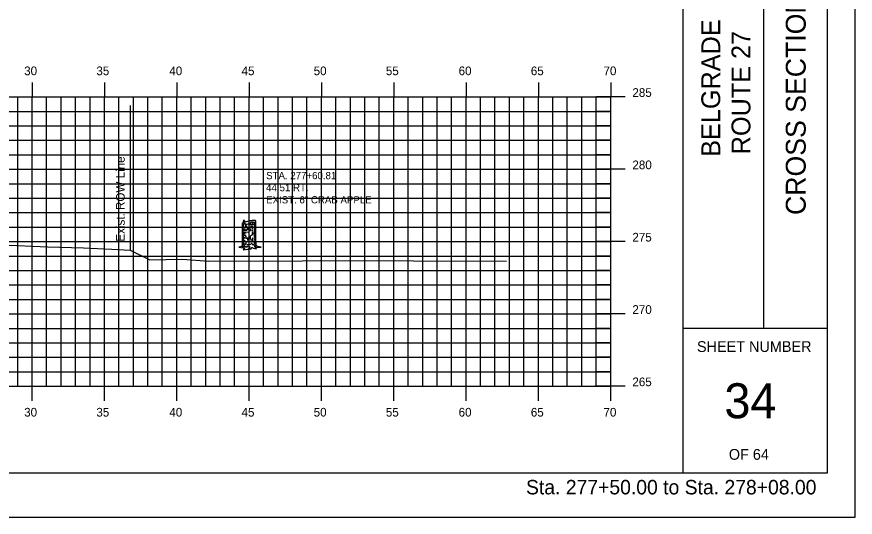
# Model space of a CAD drawing. Extents: x 854453 to 854623, y 366268 to 366378.
# Drawn here: x 854565.4 to 854623.3, y 366268.2 to 366302.8 of the extents above; entities that cross this region are included whole.
import ezdxf

# ---------------------------------------------------------------- set-up
doc = ezdxf.new("R2010")
doc.units = 0
for name, color, linetype in [('BORDER', 7, 'Continuous'), ('D_Text_Monospaced', 7, 'Continuous'), ('E_ROW_Line', 7, 'Continuous'), ('H_V ANNOTATION', 7, 'Continuous'), ('HIGHWAY_TITLE', 7, 'Continuous'), ('MAJOR', 7, 'Continuous'), ('MINOR', 7, 'Continuous'), ('PLOT BOUNDARY', 7, 'Continuous'), ('S_Roadway_Centerline', 7, 'Continuous'), ('S_Trees_Decid_NonPay', 7, 'Continuous')]:
    doc.layers.add(name, color=color, linetype=linetype)

msp = doc.modelspace()

# ---------------------------------------------------------------- linework, layer by layer
at = {"layer": 'BORDER'}
for p, q in [((854611.439, 366271.236), (854611.439, 366376.239)), ((854621.439, 366271.236), (854621.439, 366376.236)), ((854617.03, 366281.239), (854617.03, 366316.239)), ((854611.439, 366281.239), (854621.439, 366281.239)), ((854461.439, 366271.236), (854621.439, 366271.236))]:
    msp.add_line(p, q, dxfattribs=at)
at = {"layer": 'E_ROW_Line'}
msp.add_line((854573.24, 366286.634), (854573.24, 366296.634), dxfattribs=at)
at = {"layer": 'MAJOR'}
for p, q in [((854566.439, 366298.238), (854566.439, 366297.236)), ((854571.439, 366298.238), (854571.439, 366297.236)), ((854576.439, 366298.238), (854576.439, 366297.236)), ((854581.439, 366298.238), (854581.439, 366297.236)), ((854586.439, 366298.238), (854586.439, 366297.236)), ((854591.439, 366298.238), (854591.439, 366297.236)), ((854596.439, 366298.238), (854596.439, 366297.236)), ((854601.439, 366298.238), (854601.439, 366297.236)), ((854606.439, 366298.238), (854606.439, 366297.236)), ((854466.439, 366297.236), (854606.439, 366297.236)), ((854466.439, 366297.236), (854606.439, 366297.236)), ((854566.439, 366277.236), (854566.439, 366297.236)), ((854571.439, 366277.236), (854571.439, 366297.236)), ((854576.439, 366277.236), (854576.439, 366297.236)), ((854581.439, 366277.236), (854581.439, 366297.236)), ((854586.439, 366277.236), (854586.439, 366297.236)), ((854591.439, 366277.236), (854591.439, 366297.236)), ((854596.439, 366277.236), (854596.439, 366297.236)), ((854601.439, 366277.236), (854601.439, 366297.236)), ((854607.441, 366297.236), (854605.437, 366297.236)), ((854606.439, 366277.236), (854606.439, 366297.236)), ((854606.439, 366277.236), (854606.439, 366297.236)), ((854466.439, 366292.236), (854606.439, 366292.236)), ((854607.441, 366292.236), (854605.437, 366292.236)), ((854466.439, 366287.236), (854606.439, 366287.236)), ((854607.441, 366287.236), (854605.437, 366287.236)), ((854466.439, 366282.236), (854606.439, 366282.236)), ((854607.441, 366282.236), (854605.437, 366282.236)), ((854466.439, 366277.236), (854606.439, 366277.236)), ((854466.439, 366277.236), (854606.439, 366277.236)), ((854566.439, 366276.234), (854566.439, 366277.236)), ((854571.439, 366276.234), (854571.439, 366277.236)), ((854576.439, 366276.234), (854576.439, 366277.236)), ((854581.439, 366276.234), (854581.439, 366277.236)), ((854586.439, 366276.234), (854586.439, 366277.236)), ((854591.439, 366276.234), (854591.439, 366277.236)), ((854596.439, 366276.234), (854596.439, 366277.236)), ((854601.439, 366276.234), (854601.439, 366277.236)), ((854607.441, 366277.236), (854605.437, 366277.236)), ((854606.439, 366276.234), (854606.439, 366277.236))]:
    msp.add_line(p, q, dxfattribs=at)
at = {"layer": 'MINOR'}
for p, q in [((854565.439, 366277.236), (854565.439, 366297.236)), ((854567.439, 366277.236), (854567.439, 366297.236)), ((854568.439, 366277.236), (854568.439, 366297.236)), ((854569.439, 366277.236), (854569.439, 366297.236)), ((854570.439, 366277.236), (854570.439, 366297.236)), ((854572.439, 366277.236), (854572.439, 366297.236)), ((854573.439, 366277.236), (854573.439, 366297.236)), ((854574.439, 366277.236), (854574.439, 366297.236)), ((854575.439, 366277.236), (854575.439, 366297.236)), ((854577.439, 366277.236), (854577.439, 366297.236)), ((854578.439, 366277.236), (854578.439, 366297.236)), ((854579.439, 366277.236), (854579.439, 366297.236)), ((854580.439, 366277.236), (854580.439, 366297.236)), ((854582.439, 366277.236), (854582.439, 366297.236)), ((854583.439, 366277.236), (854583.439, 366297.236)), ((854584.439, 366277.236), (854584.439, 366297.236)), ((854585.439, 366277.236), (854585.439, 366297.236)), ((854587.439, 366277.236), (854587.439, 366297.236)), ((854588.439, 366277.236), (854588.439, 366297.236)), ((854589.439, 366277.236), (854589.439, 366297.236)), ((854590.439, 366277.236), (854590.439, 366297.236)), ((854592.439, 366277.236), (854592.439, 366297.236)), ((854593.439, 366277.236), (854593.439, 366297.236)), ((854594.439, 366277.236), (854594.439, 366297.236)), ((854595.439, 366277.236), (854595.439, 366297.236)), ((854597.439, 366277.236), (854597.439, 366297.236)), ((854598.439, 366277.236), (854598.439, 366297.236)), ((854599.439, 366277.236), (854599.439, 366297.236)), ((854600.439, 366277.236), (854600.439, 366297.236)), ((854602.439, 366277.236), (854602.439, 366297.236)), ((854603.439, 366277.236), (854603.439, 366297.236)), ((854604.439, 366277.236), (854604.439, 366297.236)), ((854605.439, 366277.236), (854605.439, 366297.236)), ((854466.439, 366296.236), (854606.439, 366296.236)), ((854606.439, 366296.236), (854605.437, 366296.236)), ((854466.439, 366295.236), (854606.439, 366295.236)), ((854606.439, 366295.236), (854605.437, 366295.236)), ((854466.439, 366294.236), (854606.439, 366294.236)), ((854606.439, 366294.236), (854605.437, 366294.236)), ((854466.439, 366293.236), (854606.439, 366293.236)), ((854606.439, 366293.236), (854605.437, 366293.236)), ((854466.439, 366291.236), (854606.439, 366291.236)), ((854606.439, 366291.236), (854605.437, 366291.236)), ((854466.439, 366290.236), (854606.439, 366290.236)), ((854606.439, 366290.236), (854605.437, 366290.236)), ((854466.439, 366289.236), (854606.439, 366289.236)), ((854606.439, 366289.236), (854605.437, 366289.236)), ((854466.439, 366288.236), (854606.439, 366288.236)), ((854606.439, 366288.236), (854605.437, 366288.236)), ((854466.439, 366286.236), (854606.439, 366286.236)), ((854606.439, 366286.236), (854605.437, 366286.236)), ((854466.439, 366285.236), (854606.439, 366285.236)), ((854606.439, 366285.236), (854605.437, 366285.236)), ((854466.439, 366284.236), (854606.439, 366284.236)), ((854606.439, 366284.236), (854605.437, 366284.236)), ((854466.439, 366283.236), (854606.439, 366283.236)), ((854606.439, 366283.236), (854605.437, 366283.236)), ((854466.439, 366281.236), (854606.439, 366281.236)), ((854606.439, 366281.236), (854605.437, 366281.236)), ((854466.439, 366280.236), (854606.439, 366280.236)), ((854606.439, 366280.236), (854605.437, 366280.236)), ((854466.439, 366279.236), (854606.439, 366279.236)), ((854606.439, 366279.236), (854605.437, 366279.236)), ((854466.439, 366278.236), (854606.439, 366278.236)), ((854606.439, 366278.236), (854605.437, 366278.236))]:
    msp.add_line(p, q, dxfattribs=at)
at = {"layer": 'PLOT BOUNDARY'}
msp.add_lwpolyline([(854453.345, 366268.177), (854623.345, 366268.177), (854623.345, 366378.177), (854453.345, 366378.177)], close=True, dxfattribs=at)
at = {"layer": 'S_Roadway_Centerline'}
msp.add_lwpolyline([(854564.329, 366287.018), (854567.532, 366286.879), (854569.995, 366286.803), (854571.946, 366286.719), (854573.209, 366286.65), (854574.572, 366285.978), (854576.823, 366286.018), (854578.659, 366285.881), (854585.109, 366285.897), (854586.368, 366285.929), (854599.234, 366285.884)], dxfattribs=at)
at = {"layer": 'S_Trees_Decid_NonPay'}
for p, q in [((854580.991, 366288.353), (854580.991, 366288.271)), ((854581.018, 366288.424), (854581.018, 366288.206)), ((854581.06, 366288.418), (854581.06, 366288.366)), ((854581.06, 366288.263), (854581.06, 366288.181)), ((854581.131, 366288.245), (854581.131, 366288.158)), ((854581.218, 366288.429), (854581.218, 366288.35)), ((854581.218, 366288.263), (854581.218, 366288.179)), ((854581.335, 366288.245), (854581.335, 366288.045)), ((854581.515, 366288.481), (854581.515, 366288.374)), ((854581.662, 366288.527), (854581.662, 366288.379)), ((854581.662, 366288.331), (854581.662, 366288.162)), ((854581.781, 366288.51), (854581.781, 366288.21)), ((854581.849, 366288.597), (854581.849, 366288.502)), ((854581.849, 366288.276), (854581.849, 366288.193)), ((854580.991, 366288.202), (854580.991, 366288.072)), ((854580.991, 366288.05), (854580.991, 366287.868)), ((854580.991, 366287.821), (854580.991, 366287.574)), ((854581.018, 366288.137), (854581.018, 366287.985)), ((854581.018, 366287.88), (854581.018, 366287.802)), ((854581.018, 366287.775), (854581.018, 366287.668)), ((854581.06, 366288.146), (854581.06, 366288.072)), ((854581.06, 366288.045), (854581.06, 366287.985)), ((854581.06, 366287.932), (854581.06, 366287.751)), ((854581.06, 366287.719), (854581.06, 366287.637)), ((854581.131, 366288.088), (854581.131, 366287.967)), ((854581.131, 366287.891), (854581.131, 366287.777)), ((854581.131, 366287.716), (854581.131, 366287.634)), ((854581.218, 366288.068), (854581.218, 366287.967)), ((854581.218, 366287.882), (854581.218, 366287.806)), ((854581.515, 366288.146), (854581.515, 366288.059)), ((854581.515, 366288.025), (854581.515, 366287.954)), ((854581.662, 366287.856), (854581.662, 366287.708)), ((854581.781, 366288.181), (854581.781, 366288.05)), ((854581.781, 366288.015), (854581.781, 366287.735)), ((854581.781, 366287.664), (854581.781, 366287.52)), ((854581.849, 366288.124), (854581.849, 366287.872)), ((854581.849, 366287.79), (854581.849, 366287.559)), ((854580.989, 366287.407), (854580.99, 366287.147)), ((854580.991, 366287.555), (854580.991, 366287.46)), ((854580.991, 366287.109), (854580.991, 366287.034)), ((854581.018, 366287.634), (854581.018, 366287.532)), ((854581.018, 366287.507), (854581.018, 366287.324)), ((854581.018, 366287.221), (854581.018, 366287.03)), ((854581.06, 366287.584), (854581.06, 366287.413)), ((854581.06, 366287.38), (854581.06, 366287.1)), ((854581.131, 366287.547), (854581.131, 366287.45)), ((854581.131, 366287.321), (854581.131, 366287.221)), ((854581.131, 366287.092), (854581.131, 366287.034)), ((854581.218, 366287.621), (854581.218, 366287.524)), ((854581.218, 366287.199), (854581.218, 366286.975)), ((854581.335, 366287.508), (854581.335, 366287.321)), ((854581.335, 366287.29), (854581.335, 366287.237)), ((854581.515, 366287.621), (854581.515, 366287.399)), ((854581.662, 366287.438), (854581.662, 366287.285)), ((854581.781, 366287.45), (854581.781, 366287.308)), ((854581.781, 366287.207), (854581.781, 366287.026)), ((854581.849, 366287.489), (854581.849, 366287.328)), ((854581.849, 366287.312), (854581.849, 366287.207)), ((854581.849, 366287.17), (854581.849, 366287.046)), ((854580.938, 366286.861), (854581.005, 366286.892)), ((854581.02, 366286.983), (854580.985, 366286.931)), ((854581.06, 366287.048), (854581.06, 366287.022)), ((854581.335, 366287.061), (854581.335, 366286.97)), ((854581.475, 366286.779), (854581.51, 366286.925)), ((854581.515, 366287.065), (854581.515, 366286.999)), ((854581.662, 366287.073), (854581.662, 366286.995)), ((854581.781, 366286.966), (854581.823, 366286.87))]:
    msp.add_line(p, q, dxfattribs=at)
for points in [[(854580.949, 366288.461), (854580.949, 366287.049), (854580.927, 366286.901), (854580.724, 366286.857), (854580.863, 366286.822), (854581.082, 366286.803), (854581.152, 366286.76), (854581.03, 366286.672), (854581.361, 366286.715), (854581.475, 366286.779), (854581.568, 366286.719), (854581.623, 366286.798), (854581.615, 366286.834), (854581.676, 366286.836), (854581.728, 366286.779), (854581.961, 366286.727), (854581.833, 366286.816), (854581.965, 366286.818), (854582.274, 366286.855), (854582.035, 366286.886), (854581.957, 366286.944), (854581.918, 366287.065), (854581.901, 366287.419), (854581.901, 366288.653)], [(854581.045, 366288.542), (854581.049, 366288.636), (854581.063, 366288.609), (854581.063, 366288.731), (854581.084, 366288.667), (854581.098, 366288.7), (854581.115, 366288.644), (854581.131, 366288.661), (854581.15, 366288.653), (854581.169, 366288.586)], [(854581.067, 366288.418), (854581.084, 366288.479), (854581.106, 366288.467), (854581.137, 366288.502), (854581.171, 366288.424)], [(854581.537, 366288.487), (854581.545, 366288.553), (854581.57, 366288.558), (854581.578, 366288.593), (854581.609, 366288.578), (854581.623, 366288.593), (854581.648, 366288.57), (854581.671, 366288.578), (854581.683, 366288.628), (854581.691, 366288.584), (854581.722, 366288.593), (854581.725, 366288.542)], [(854580.989, 366286.908), (854581.068, 366286.892), (854581.084, 366286.849)], [(854581.068, 366286.892), (854581.111, 366286.927), (854581.119, 366286.975)], [(854581.215, 366286.927), (854581.209, 366286.857), (854581.146, 366286.845)], [(854581.327, 366286.921), (854581.327, 366286.884), (854581.276, 366286.853), (854581.258, 366286.803)], [(854581.852, 366287.004), (854581.86, 366286.927), (854581.938, 366286.878)]]:
    msp.add_lwpolyline(points, dxfattribs=at)
for centre, radius, start, end in [((854580.973, 366288.461), 0.0237, 161.82771, 175.77218), ((854580.968, 366288.461), 0.0179, 175.77218, 191.82771), ((854580.968, 366288.461), 0.0179, 191.82771, 207.88324), ((854580.97, 366288.392), 0.0191, 173.88724, 180), ((854580.97, 366288.392), 0.0191, 180, 196.05154), ((854580.97, 366288.291), 0.0191, 173.88724, 180), ((854580.97, 366288.291), 0.0191, 180, 196.05154), ((854580.983, 366288.457), 0.0336, 143.05141, 161.82771), ((854580.975, 366288.394), 0.0252, 196.05154, 210), ((854580.975, 366288.293), 0.0252, 196.05154, 210), ((854580.973, 366288.464), 0.0237, 207.88324, 221.82771), ((854580.984, 366288.399), 0.0356, 210, 228.74941), ((854580.984, 366288.298), 0.0356, 210, 228.74941), ((854580.98, 366288.47), 0.0336, 221.82771, 240.60401), ((854581.031, 366288.421), 0.0935, 131.82771, 143.0514), ((854581.026, 366288.446), 0.0984, 228.74941, 240), ((854581.026, 366288.345), 0.0984, 228.74941, 240), ((854581.01, 366288.522), 0.0935, 240.60401, 251.82771), ((854581.183, 366288.251), 0.322, 109.70976, 131.82771), ((854581.14, 366288.643), 0.326, 240, 248.04943), ((854581.14, 366288.542), 0.326, 240, 248.04943), ((854581.081, 366288.739), 0.322, 251.82771, 267.55213), ((854581.92, 366286.194), 2.507, 101.82771, 109.70976), ((854581.426, 366290.653), 2.356, 263.22662, 266.85193), ((854580.93, 366290.919), 2.507, 275.49866, 281.82771), ((854581.92, 366286.194), 2.507, 93.94565, 101.82771), ((854580.93, 366290.919), 2.507, 281.82771, 284.00133), ((854581.426, 366290.767), 2.356, 272.16143, 274.75999), ((854581.426, 366290.653), 2.356, 272.63272, 275.75799), ((854581.426, 366290.767), 2.356, 276.72009, 278.1032), ((854580.93, 366290.919), 2.507, 288.47191, 289.70976), ((854581.77, 366288.374), 0.322, 71.82771, 93.94565), ((854581.712, 366288.756), 0.326, 278.1032, 282.1964), ((854581.667, 366288.862), 0.322, 289.70976, 311.82771), ((854581.712, 366288.643), 0.326, 282.1964, 299.09011), ((854581.712, 366288.756), 0.326, 291.67568, 300), ((854581.712, 366288.542), 0.326, 296.42813, 300), ((854581.841, 366288.591), 0.0935, 60.60401, 71.82771), ((854581.826, 366288.559), 0.0984, 300, 311.25059), ((854581.826, 366288.345), 0.0984, 300, 311.25059), ((854581.82, 366288.692), 0.0935, 311.82771, 323.0514), ((854581.87, 366288.643), 0.0336, 41.82771, 60.60401), ((854581.867, 366288.512), 0.0356, 311.25059, 330), ((854581.867, 366288.298), 0.0356, 311.25059, 330), ((854581.867, 366288.656), 0.0336, 323.05141, 341.82771), ((854581.878, 366288.65), 0.0237, 27.88324, 41.82771), ((854581.876, 366288.507), 0.0252, 330, 343.94846), ((854581.876, 366288.293), 0.0252, 330, 343.94846), ((854581.883, 366288.653), 0.0179, 11.82771, 27.88324), ((854581.877, 366288.653), 0.0237, 341.82771, 355.77218), ((854581.883, 366288.653), 0.0179, 355.77218, 11.82771), ((854581.882, 366288.505), 0.0191, 0, 16.05154), ((854581.882, 366288.505), 0.0191, 343.94846, 0), ((854581.882, 366288.291), 0.0191, 0, 16.05154), ((854581.882, 366288.291), 0.0191, 343.94846, 0), ((854580.97, 366288.188), 0.0191, 173.88724, 180), ((854580.97, 366288.188), 0.0191, 180, 196.05154), ((854580.97, 366288.083), 0.0191, 173.88724, 180), ((854580.97, 366288.083), 0.0191, 180, 196.05154), ((854580.97, 366287.968), 0.0191, 173.88724, 180), ((854580.97, 366287.968), 0.0191, 180, 196.05154), ((854580.969, 366287.854), 0.0191, 173.88723, 180), ((854580.969, 366287.854), 0.0191, 180, 196.05154), ((854580.975, 366287.855), 0.0252, 196.05154, 210), ((854580.975, 366288.085), 0.0252, 196.05154, 210), ((854580.975, 366287.97), 0.0252, 196.05154, 210), ((854580.984, 366287.861), 0.0356, 210, 228.74941), ((854580.972, 366287.753), 0.0191, 173.88723, 180), ((854580.972, 366287.753), 0.0191, 180, 196.05154), ((854580.984, 366288.09), 0.0356, 210, 228.74941), ((854580.984, 366287.975), 0.0356, 210, 228.74941), ((854580.978, 366287.755), 0.0252, 196.05154, 210), ((854580.987, 366287.76), 0.0356, 210, 228.74941), ((854581.025, 366287.908), 0.0984, 228.74941, 240), ((854581.026, 366288.137), 0.0984, 228.74941, 240), ((854581.026, 366288.022), 0.0984, 228.74941, 240), ((854581.028, 366287.807), 0.0984, 228.74941, 240), ((854581.139, 366288.105), 0.326, 240, 242.99417), ((854581.14, 366288.334), 0.326, 240, 248.04943), ((854581.14, 366288.219), 0.326, 240, 255.96177), ((854581.142, 366288.005), 0.326, 240, 247.59507), ((854581.139, 366288.105), 0.326, 248.19018, 256.09636), ((854581.14, 366288.439), 0.326, 255.96177, 261.8968), ((854581.14, 366288.334), 0.326, 255.96177, 261.8968), ((854581.14, 366288.542), 0.326, 260.91457, 261.8968), ((854581.426, 366290.552), 2.356, 261.8968, 264.93532), ((854581.426, 366290.449), 2.356, 261.8968, 262.61616), ((854581.426, 366290.344), 2.356, 261.8968, 262.81315), ((854581.426, 366290.229), 2.356, 262.81315, 264.93533), ((854581.428, 366290.015), 2.356, 262.75446, 265.02656), ((854581.426, 366290.344), 2.356, 264.93533, 266.9933), ((854581.426, 366290.449), 2.356, 266.02592, 267.8019), ((854581.426, 366290.229), 2.356, 267.586, 270), ((854581.426, 366290.552), 2.356, 267.8019, 269.18812), ((854581.426, 366290.229), 2.356, 270, 270.44221), ((854581.426, 366290.449), 2.356, 272.16143, 273.49644), ((854581.428, 366290.015), 2.356, 273.14712, 275.6557), ((854581.426, 366290.344), 2.356, 274.36383, 276.73183), ((854581.426, 366290.449), 2.356, 275.00538, 276.65871), ((854581.426, 366290.229), 2.356, 275.20886, 277.34123), ((854581.425, 366290.115), 2.356, 277.13849, 278.1032), ((854581.426, 366290.552), 2.356, 277.44809, 278.1032), ((854581.711, 366288.105), 0.326, 278.1032, 282.33006), ((854581.712, 366288.542), 0.326, 278.1032, 289.58325), ((854581.712, 366288.439), 0.326, 282.1964, 288.31694), ((854581.712, 366288.334), 0.326, 282.1964, 294.84552), ((854581.714, 366288.005), 0.326, 283.09214, 300), ((854581.711, 366288.105), 0.326, 292.13442, 300), ((854581.712, 366288.219), 0.326, 294.84552, 300), ((854581.712, 366288.439), 0.326, 296.75697, 300), ((854581.825, 366287.908), 0.0984, 300, 311.25059), ((854581.826, 366288.242), 0.0984, 300, 311.25059), ((854581.826, 366288.022), 0.0984, 300, 311.25059), ((854581.867, 366287.861), 0.0356, 311.25059, 330), ((854581.867, 366288.195), 0.0356, 311.25059, 330), ((854581.867, 366287.975), 0.0356, 311.25059, 330), ((854581.876, 366287.855), 0.0252, 330, 343.94846), ((854581.876, 366288.19), 0.0252, 330, 343.94846), ((854581.876, 366287.97), 0.0252, 330, 343.94846), ((854581.882, 366287.854), 0.0191, 0, 16.05154), ((854581.882, 366287.854), 0.0191, 343.94846, 0), ((854581.882, 366288.188), 0.0191, 0, 16.05154), ((854581.882, 366288.188), 0.0191, 343.94846, 0), ((854581.882, 366287.968), 0.0191, 0, 16.05154), ((854581.882, 366287.968), 0.0191, 343.94846, 0), ((854581.885, 366287.753), 0.0191, 0, 16.05154), ((854580.97, 366287.649), 0.0191, 173.88724, 180), ((854580.97, 366287.649), 0.0191, 180, 196.05154), ((854580.97, 366287.558), 0.0191, 173.88724, 180), ((854580.975, 366287.65), 0.0252, 196.05154, 210), ((854580.984, 366287.656), 0.0356, 210, 228.74941), ((854580.974, 366287.33), 0.0191, 173.88724, 180), ((854580.974, 366287.33), 0.0191, 180, 196.05154), ((854580.979, 366287.331), 0.0252, 196.05154, 210), ((854580.989, 366287.337), 0.0356, 210, 228.74941), ((854581.026, 366287.703), 0.0984, 228.74941, 240), ((854581.03, 366287.384), 0.0984, 228.74941, 240), ((854580.984, 366287.109), 0.0191, 173.88723, 180), ((854580.984, 366287.109), 0.0191, 180, 196.05154), ((854580.99, 366287.11), 0.0252, 196.05154, 210), ((854580.999, 366287.116), 0.0356, 210, 228.74941), ((854581.04, 366287.163), 0.0984, 228.74941, 240), ((854581.14, 366287.9), 0.326, 240, 242.84748), ((854581.149, 366287.47), 0.326, 240, 246.3456), ((854581.14, 366287.9), 0.326, 248.04943, 255.96177), ((854581.14, 366287.696), 0.326, 248.04943, 255.96177), ((854581.144, 366287.581), 0.326, 255.22586, 261.8968), ((854581.43, 366289.591), 2.356, 261.8968, 262.71371), ((854581.426, 366289.91), 2.356, 263.57201, 264.93533), ((854581.426, 366289.819), 2.356, 264.72741, 267.8019), ((854581.435, 366289.48), 2.356, 264.71707, 265.81357), ((854581.426, 366289.91), 2.356, 270.99458, 272.16143), ((854581.426, 366289.706), 2.356, 272.53097, 275.75799), ((854581.435, 366289.48), 2.356, 273.18422, 275.09113), ((854581.426, 366289.819), 2.356, 275.51349, 277.41567), ((854581.43, 366289.591), 2.356, 275.5148, 277.77742), ((854581.712, 366287.809), 0.326, 286.0817, 298.06104), ((854581.712, 366287.9), 0.326, 294.84552, 300), ((854581.716, 366287.581), 0.326, 294.06251, 300), ((854581.727, 366287.36), 0.326, 292.0839, 300), ((854581.826, 366287.703), 0.0984, 300, 311.25059), ((854581.721, 366287.47), 0.326, 298.09031, 300), ((854581.83, 366287.384), 0.0984, 300, 311.25059), ((854581.835, 366287.273), 0.0984, 300, 311.25059), ((854581.84, 366287.163), 0.0984, 300, 311.25059), ((854581.867, 366287.656), 0.0356, 311.25059, 330), ((854581.871, 366287.337), 0.0356, 311.25059, 330), ((854581.876, 366287.65), 0.0252, 330, 343.94846), ((854581.876, 366287.226), 0.0356, 311.25059, 330), ((854581.882, 366287.649), 0.0191, 0, 16.05154), ((854581.882, 366287.649), 0.0191, 343.94846, 0), ((854581.88, 366287.331), 0.0252, 330, 343.94846), ((854581.886, 366287.33), 0.0191, 0, 16.05154), ((854581.886, 366287.33), 0.0191, 343.94846, 0), ((854581.882, 366287.116), 0.0356, 311.25059, 330), ((854581.885, 366287.221), 0.0252, 330, 343.94846), ((854581.891, 366287.219), 0.0191, 0, 16.05154), ((854581.891, 366287.219), 0.0191, 343.94846, 0), ((854581.891, 366287.11), 0.0252, 330, 343.94846), ((854581.897, 366287.109), 0.0191, 0, 16.05154), ((854581.897, 366287.109), 0.0191, 343.94846, 0), ((854581.154, 366287.36), 0.326, 245.29062, 261.8968), ((854581.44, 366289.37), 2.356, 261.8968, 262.45968), ((854581.44, 366289.37), 2.356, 264.5833, 265.44488), ((854581.44, 366289.37), 2.356, 276.46672, 278.1032), ((854581.727, 366287.36), 0.326, 278.1032, 279.61658)]:
    msp.add_arc(centre, radius, start, end, dxfattribs=at)

# ---------------------------------------------------------------- texts
at = {"layer": 'BORDER'}
for s, height, rotation, p in [('CROSS SECTIONS', 1.37787, 90, (854619.923, 366289.073)), ('SHEET NUMBER', 0.74527, 360, (854612.404, 366279.603)), ('34', 2.4194, 360, (854614.3, 366275.019)), ('OF 64', 0.7453, 360, (854614.606, 366272.149))]:
    msp.add_text(s, height=height, rotation=rotation, dxfattribs=at).set_placement(p)
at = {"layer": 'D_Text_Monospaced'}
for s, height, p in [('STA. 277+60.81', 0.49998, (854582.616, 366291.547)), ('44.51 RT.', 0.5, (854582.616, 366290.713)), ('EXIST. 6" CRAB APPLE', 0.49998, (854582.616, 366289.873))]:
    msp.add_text(s, height=height, dxfattribs=at).set_placement(p)
at = {"layer": 'E_ROW_Line'}
msp.add_text('Exist. ROW Line', height=0.6, rotation=90, dxfattribs=at).set_placement((854572.84, 366287.234))
at = {"layer": 'H_V ANNOTATION'}
for s, height, p in [('30', 0.6, (854565.887, 366298.736)), ('35', 0.6, (854570.879, 366298.736)), ('40', 0.6, (854575.925, 366298.736)), ('45', 0.6, (854580.917, 366298.736)), ('50', 0.6, (854585.903, 366298.736)), ('55', 0.6, (854590.895, 366298.736)), ('60', 0.6, (854595.925, 366298.736)), ('65', 0.6, (854600.917, 366298.736)), ('70', 0.6, (854605.941, 366298.736)), ('285', 0.6, (854607.939, 366297.236)), ('280', 0.6, (854607.939, 366292.236)), ('275', 0.6, (854607.939, 366287.236)), ('270', 0.6, (854607.939, 366282.236)), ('265', 0.6, (854607.939, 366277.236)), ('30', 0.6, (854565.887, 366275.136)), ('35', 0.6, (854570.879, 366275.136)), ('40', 0.6, (854575.925, 366275.136)), ('45', 0.6, (854580.917, 366275.136)), ('50', 0.6, (854585.903, 366275.136)), ('55', 0.6, (854590.895, 366275.136)), ('60', 0.6, (854595.925, 366275.136)), ('65', 0.6, (854600.917, 366275.136)), ('70', 0.6, (854605.941, 366275.136)), ('Sta. 277+50.00 to Sta. 278+08.00', 1.0002, (854600.584, 366269.756))]:
    msp.add_text(s, height=height, dxfattribs=at).set_placement(p)
at = {"layer": 'HIGHWAY_TITLE'}
for s, p in [('BELGRADE', (854614.011, 366293.095)), ('ROUTE 27', (854616.098, 366293.269))]:
    msp.add_text(s, height=1.3043, rotation=90, dxfattribs=at).set_placement(p)

doc.saveas('drawing.dxf')
